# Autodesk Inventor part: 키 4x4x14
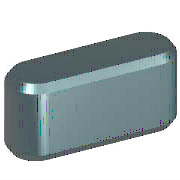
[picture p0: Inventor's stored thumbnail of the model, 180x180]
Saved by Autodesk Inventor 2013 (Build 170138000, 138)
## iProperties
IsCustomPart: 1
Created: 2012-02
Part Number: 키 4x4x14
Material: 강철, 연강
Description: 키 및 해당 키홈
Document SubType Name: Modeling
Standard: KS B 1311
Designer: mduedu
Standards Organization: KS
Language: ko-KR
Size Designation: 4 x 4 x 14
Categories: <MemberInstance><Categories><Category DisplayName="샤프트 부품" InternalName="7f7aeb1f-a693-4053-b835-cee3144e0d98" Mnemonic="SHFT"><Category DisplayName="키" Interna
Density: 1 g/cm^3
Author: mduedu
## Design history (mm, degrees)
workplane "Work Plane1"
workplane "Work Plane2"
sketch "스케치1"
  geometry: L1 (2, 2)-(12, 2); L2 (12, -2)-(2, -2); L3 (0, 9.4)-(0, -7.4) reference; L4 (-5, 0)-(30, 0) reference; L5 (14, 0)-(14, 7); A1 r 2 centre (2, 0) between (2, 2) and (2, -2); A2 r 2 centre (12, 0) between (12, -2) and (12, 2)
  constraints: 6 end point, 5 point on circle, 4 tangent, 3 point on line, 2 centre point, 1 horizontal, 1 parallel, 1 perpendicular
  dimensions: "d0" = 2 radius of A1 (= 0.5 x PB); "d13" = 2 radius of A2 (= 0.5 x PB); "d14" = 14 distance between parallel lines of L5 L3 (= NLG)
extrude "본체1" new body sketch "스케치1" taper "d3" = 0 deg; stored distance "d4" = 10
workplane "Work Plane3"
body "Solid1"
chamfer "모따기1" distance "d8" = 0.25 (= PHH); stored, may be unused: second distance "d9" = 0.25 (= PHH), angle "d15" = 45 deg
other parameters: "d1" = -2.5 (= -PNT), "d2" = 1.5 (= PH - PNT), "NLG" = 14 [user parameter; used in 3 equation terms], "PB" = 4 [user parameter; used in 2 equation terms], "PNT" = 2.5 [user parameter; used in 2 equation terms], "PH" = 4 [user parameter; used in 1 equation term], "PHH" = 0.25 [user parameter; used in 2 equation terms], "d10" = 0, "d16" = 0, "d17" = 0, "d18" = 0, "PLB2" = 14 (= NLG) [user parameter], "WDMAX" = 12 [user parameter], "PLB1" = 14 (= NLG) [user parameter], "RR" = 0.08 [user parameter], "PUEB" = 1.8 [user parameter]
